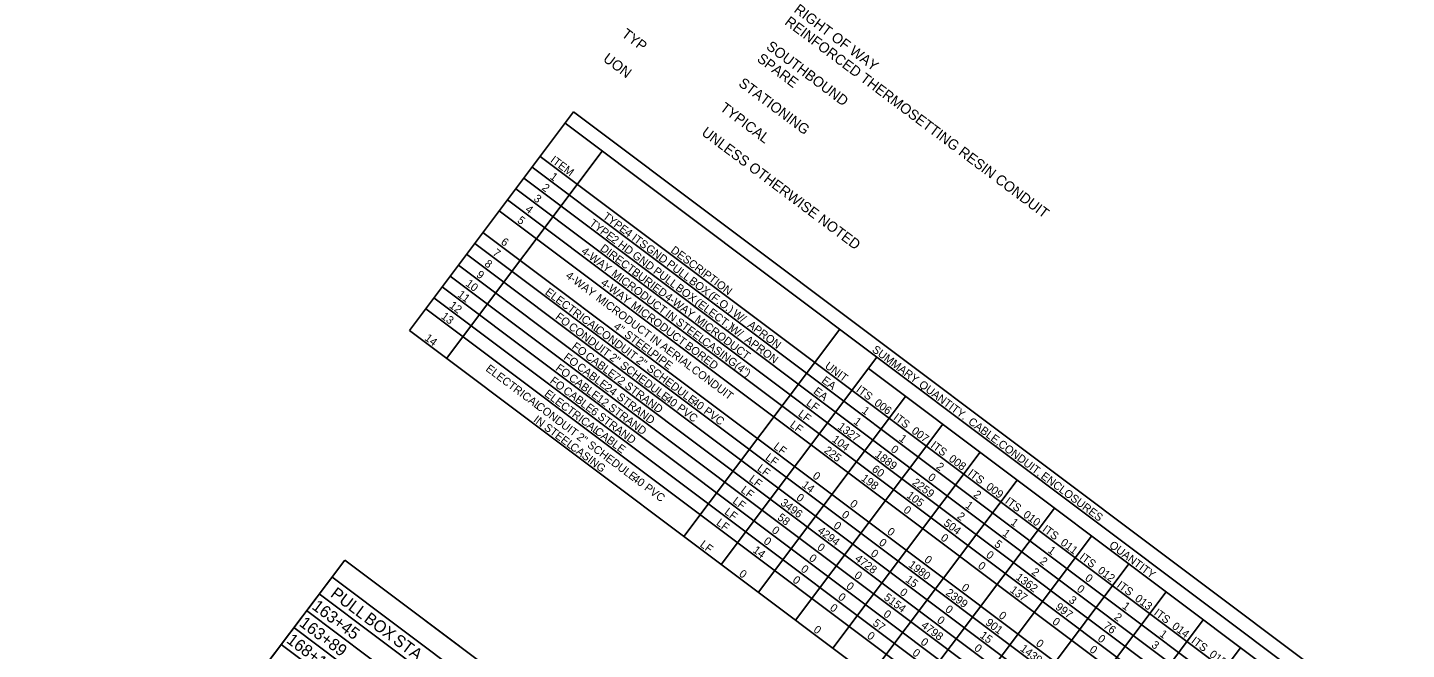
# Model space of a CAD drawing. Extents: x 626494 to 629419, y 365986 to 369334.
# Drawn here: x 627800.6 to 628284.5, y 368394.1 to 368612.5 of the extents above; entities that cross this region are included whole.
import ezdxf

# ---------------------------------------------------------------- set-up
doc = ezdxf.new("R2010")
doc.units = 0
for name, color, linetype in [('Default', 7, 'Continuous'), ('R_No Plot', 7, 'Continuous'), ('R_Shade Frontage Road', 7, 'Continuous')]:
    doc.layers.add(name, color=color, linetype=linetype)

msp = doc.modelspace()

# ---------------------------------------------------------------- linework, layer by layer
at = {"layer": 'Default'}
for p, q in [((627934.57, 368506.14), (627992.22, 368582.9)), ((627992.22, 368582.9), (627992.22, 368582.9)), ((627992.22, 368582.9), (628284.46, 368363.46)), ((627989.23, 368578.92), (628281.47, 368359.47)), ((627947.63, 368496.33), (628002.29, 368569.11)), ((627977.63, 368563.47), (628269.87, 368344.03)), ((627980.5, 368567.29), (628272.74, 368347.85)), ((627974.76, 368559.65), (628267, 368340.2)), ((627971.89, 368555.83), (628264.13, 368336.38)), ((627969.02, 368552.01), (628261.26, 368332.56)), ((627966.15, 368548.18), (628258.39, 368328.74)), ((627960.41, 368540.54), (628252.65, 368321.09)), ((627957.54, 368536.72), (628249.78, 368317.27)), ((627951.8, 368529.07), (628244.04, 368309.63)), ((627954.67, 368532.89), (628246.91, 368313.45)), ((627948.93, 368525.25), (628241.17, 368305.8)), ((627946.05, 368521.43), (628238.3, 368301.98)), ((627943.18, 368517.61), (628235.43, 368298.16)), ((627940.31, 368513.78), (628232.56, 368294.34)), ((627934.57, 368506.14), (628226.82, 368286.69)), ((628030.93, 368433.79), (628085.58, 368506.57)), ((628043.99, 368423.98), (628098.64, 368496.76)), ((628095.65, 368492.78), (628278.48, 368355.49)), ((628057.04, 368414.18), (628108.71, 368482.98)), ((628070.1, 368404.37), (628121.77, 368473.17)), ((628083.16, 368394.56), (628134.83, 368463.36)), ((628096.22, 368384.76), (628147.89, 368453.56)), ((628109.28, 368374.95), (628160.94, 368443.75)), ((628122.34, 368365.14), (628174, 368433.94)), ((627800.61, 368277.33), (627911.88, 368425.51)), ((627911.88, 368425.51), (628111.03, 368275.96)), ((628135.4, 368355.34), (628187.06, 368424.14)), ((627907.43, 368419.58), (628106.58, 368270.04)), ((627902.97, 368413.65), (628102.13, 368264.11)), ((628148.46, 368345.53), (628200.12, 368414.33)), ((627898.52, 368407.73), (628097.68, 368258.18)), ((628161.52, 368335.72), (628213.18, 368404.52)), ((627894.07, 368401.8), (628093.22, 368252.26)), ((627889.62, 368395.87), (628088.77, 368246.33)), ((628174.58, 368325.92), (628226.24, 368394.72))]:
    msp.add_line(p, q, dxfattribs=at)
at = {"layer": 'R_No Plot'}
msp.add_line((627911.88, 368425.51), (627911.88, 368425.51), dxfattribs=at)
msp.add_lwpolyline([(627911.88, 368425.51), (628234.33, 368183.37), (628185.91, 368118.88), (627863.45, 368361.02)], close=True, dxfattribs=at)

# ---------------------------------------------------------------- texts
at = {"layer": 'Default'}
for s, height, p in [('ITEM', 2.809, (627983.83, 368565.5)), ('1', 2.81, (627983.69, 368559.62)), ('3', 2.81, (627977.96, 368551.97)), ('2', 2.81, (627980.83, 368555.8)), ('4', 2.81, (627975.04, 368548.19)), ('5', 2.81, (627972.22, 368544.33)), ('TYPE', 2.809, (627997.49, 368543.28)), ('TYPE', 2.809, (628002.21, 368545.71)), (' 2', 2.809, (628004.31, 368538.16)), (' 4', 2.809, (628009.04, 368540.59)), (' ITS', 2.809, (628011.53, 368538.72)), ('7', 2.81, (627963.59, 368532.88)), ('6', 2.81, (627966.45, 368536.71)), ('4-WAY', 2.809, (627994.65, 368533.46)), ('DIRECT', 2.809, (628001.28, 368534.46)), (' HD', 2.809, (628006.71, 368536.36)), (' GND', 2.809, (628016.44, 368535.03)), ('DESCRIPTION', 2.8087, (628026.04, 368533.8)), ('8', 2.81, (627960.71, 368529.06)), (' GND', 2.809, (628011.73, 368532.59)), (' PULL', 2.809, (628023.77, 368529.52)), ('9', 2.81, (627957.86, 368525.22)), ('4-WAY', 2.809, (627989.2, 368524.89)), (' MICRODUCT', 2.809, (628004.39, 368526.15)), (' BURIED', 2.809, (628011.58, 368526.72)), (' PULL', 2.809, (628019.06, 368527.08)), (' BOX', 2.809, (628031.61, 368523.63)), ('11', 2.809, (627951.23, 368518.25)), ('10', 2.809, (627954.06, 368522.1)), ('ELECTRICAL', 2.809, (627981.95, 368519.09)), ('4-WAY', 2.809, (628001.5, 368522.34)), (' BOX', 2.809, (628026.9, 368521.19)), (' (F.O.)', 2.809, (628038.44, 368518.51)), ('12', 2.809, (627948.36, 368514.42)), (' MICRODUCT', 2.809, (627998.94, 368517.58)), (' MICRODUCT', 2.809, (628011.24, 368515.02)), (' 4-WAY', 2.809, (628023.13, 368518.05)), (' (ELECT.)', 2.809, (628033.72, 368516.07)), ('13', 2.809, (627945.5, 368510.6)), ('FO', 2.809, (627985.56, 368510.4)), (' IN', 2.809, (628023.29, 368511.95)), (' STEEL', 2.809, (628026.97, 368509.19)), (' MICRODUCT', 2.809, (628033.68, 368510.13)), (' W/', 2.809, (628046.91, 368512.15)), (' CONDUIT', 2.809, (627989.36, 368507.55)), (' CONDUIT', 2.809, (627998.71, 368506.5)), ('4"', 2.809, (628006, 368507)), (' STEEL', 2.809, (628008.94, 368504.79)), (' W/', 2.809, (628045.89, 368506.94)), (' APRON', 2.809, (628052.2, 368508.18)), ('14', 2.809, (627939.7, 368502.99)), ('FO', 2.809, (627991.39, 368500.04)), (' IN', 2.809, (628017.84, 368503.38)), (' AERIAL', 2.809, (628021.52, 368500.62)), (' BORED', 2.809, (628030.15, 368500.83)), (' CASING', 2.809, (628036.03, 368502.39)), (' APRON', 2.809, (628051.18, 368502.97)), ('SUMMARY', 2.809, (628096.7, 368498.92)), ('FO', 2.809, (627988.48, 368496.25)), (' CABLE', 2.809, (627995.19, 368497.19)), (' 2"', 2.809, (628003.71, 368496.77)), (' SCHEDULE', 2.809, (628007.45, 368493.96)), (' 2"', 2.809, (628013.06, 368495.73)), (' PIPE', 2.809, (628018.01, 368497.99)), ('UNIT', 2.809, (628080.14, 368493.17)), ('ELECTRICAL', 2.809, (627961.12, 368492.18)), ('FO', 2.809, (627985.65, 368492.4)), (' CABLE', 2.809, (627989.45, 368489.55)), (' CABLE', 2.809, (627992.27, 368493.4)), (' 72', 2.809, (628004.88, 368489.92)), (' SCHEDULE', 2.809, (628016.8, 368492.92)), (' CONDUIT', 2.809, (628032.41, 368492.44)), (' (4")', 2.809, (628047.54, 368493.74)), ('FO', 2.809, (627983.65, 368487.92)), (' CABLE', 2.809, (627987.45, 368485.07)), (' 24', 2.809, (628001.96, 368486.13)), (' STRAND', 2.809, (628009.07, 368486.77)), ('EA', 2.809, (628076.12, 368484.24)), ('EA', 2.809, (628078.99, 368488.06)), ('ITS_006', 2.809, (628091.15, 368484.9)), (' QUANTITY.', 2.809, (628112.29, 368487.22)), (' CONDUIT', 2.809, (627977.88, 368479.59)), ('ELECTRICAL', 2.809, (627981.73, 368483.38)), (' 12', 2.809, (627999.14, 368482.27)), (' STRAND', 2.809, (628006.24, 368482.91)), (' 40', 2.809, (628023.17, 368482.16)), (' 40', 2.809, (628032.52, 368481.11)), ('LF', 2.809, (628073.63, 368480.13)), ('IN', 2.809, (627977.89, 368474.32)), (' 6', 2.809, (627997.13, 368477.8)), (' STRAND', 2.809, (627999.59, 368475.96)), (' STRAND', 2.809, (628003.32, 368479.13)), (' PVC', 2.809, (628027.43, 368478.96)), (' PVC', 2.809, (628036.78, 368477.91)), ('LF', 2.809, (628070.76, 368476.31)), ('1', 2.81, (628093.1, 368477.46)), ('ITS_007', 2.809, (628104.22, 368475.09)), (' STEEL', 2.809, (627980.77, 368472.15)), (' CABLE', 2.809, (627998.49, 368470.8)), ('LF', 2.809, (628067.89, 368472.49)), ('1327', 2.809, (628084.66, 368471.85)), ('1', 2.81, (628090.23, 368473.64)), ('  CABLE,', 2.809, (628128.77, 368474.84)), (' CASING', 2.809, (627989.83, 368465.35)), (' 2"', 2.809, (627992.23, 368468.82)), (' SCHEDULE', 2.809, (627995.97, 368466.01)), ('LF', 2.809, (628062.15, 368464.84)), ('104', 2.809, (628082.66, 368467.38)), ('1', 2.81, (628106.16, 368467.66)), ('ITS_008', 2.809, (628117.27, 368465.29)), (' CONDUIT,', 2.809, (628140.08, 368466.34)), ('LF', 2.809, (628059.27, 368461.02)), ('225', 2.809, (628079.84, 368463.51)), ('1889', 2.809, (628097.73, 368462.03)), ('0', 2.81, (628103.26, 368463.86)), ('LF', 2.809, (628056.4, 368457.2)), ('0', 2.81, (628075.85, 368454.55)), ('60', 2.809, (628096.62, 368456.89)), ('2', 2.81, (628119.22, 368457.85)), ('ITS_009', 2.809, (628130.35, 368455.47)), (' ENCLOSURES', 2.8087, (628155.1, 368455.07)), (' 40', 2.809, (628011.69, 368454.2)), (' PVC', 2.809, (628015.95, 368451)), ('LF', 2.809, (628050.66, 368449.56)), ('LF', 2.809, (628053.53, 368453.38)), ('14', 2.809, (628072.07, 368451.41)), ('198', 2.809, (628092.87, 368453.73)), ('2259', 2.809, (628110.79, 368452.23)), ('0', 2.81, (628116.32, 368454.05)), ('LF', 2.809, (628047.79, 368445.73)), ('3496', 2.809, (628064.56, 368445.1)), ('0', 2.81, (628070.11, 368446.91)), ('105', 2.809, (628108.83, 368447.72)), ('2', 2.81, (628132.28, 368448.04)), ('ITS_010', 2.809, (628143.38, 368445.69)), ('LF', 2.809, (628044.92, 368441.91)), ('58', 2.809, (628063.48, 368439.93)), ('0', 2.81, (628086.04, 368440.93)), ('0', 2.81, (628088.91, 368444.75)), ('0', 2.81, (628107.71, 368442.59)), ('2', 2.81, (628126.54, 368440.4)), ('1', 2.81, (628129.41, 368444.22)), ('LF', 2.809, (628042.05, 368438.09)), ('0', 2.81, (628061.5, 368435.44)), ('0', 2.81, (628083.17, 368437.1)), ('504', 2.809, (628121.83, 368437.96)), ('1', 2.81, (628145.34, 368438.24)), ('ITS_011', 2.809, (628156.48, 368435.85)), ('LF', 2.809, (628036.31, 368430.44)), ('0', 2.81, (628058.63, 368431.62)), ('4294', 2.809, (628077.6, 368435.31)), ('0', 2.81, (628099.1, 368431.12)), ('0', 2.81, (628101.97, 368434.94)), ('0', 2.81, (628120.77, 368432.78)), ('5', 2.81, (628139.61, 368430.59)), ('1', 2.81, (628142.47, 368434.41)), ('14', 2.809, (628054.85, 368428.48)), ('0', 2.81, (628074.56, 368425.64)), ('0', 2.81, (628077.43, 368429.46)), ('0', 2.81, (628096.23, 368427.3)), ('0', 2.81, (628136.7, 368426.8)), ('1', 2.81, (628158.4, 368428.43)), ('ITS_012', 2.809, (628169.54, 368426.05)), ('QUANTITY', 2.809, (628179.9, 368430.22)), ('0', 2.81, (628071.69, 368421.82)), ('4728', 2.809, (628090.68, 368425.49)), ('1980', 2.809, (628109.47, 368423.33)), ('0', 2.81, (628115.03, 368425.14)), ('0', 2.81, (628133.83, 368422.97)), ('2', 2.81, (628152.66, 368420.78)), ('2', 2.81, (628155.53, 368424.61)), ('0', 2.81, (628050.02, 368420.15)), ('0', 2.81, (628068.82, 368417.99)), ('0', 2.81, (628087.62, 368415.83)), ('0', 2.81, (628090.49, 368419.65)), ('15', 2.809, (628108.43, 368418.13)), ('1362', 2.809, (628147.1, 368418.98)), ('0', 2.81, (628171.43, 368418.65)), ('ITS_013', 2.809, (628182.61, 368416.23)), ('PULL', 4.181, (627906.62, 368412.94)), ('0', 2.81, (628084.75, 368412.01)), ('5154', 2.809, (628100.85, 368411.87)), ('0', 2.81, (628106.42, 368413.67)), ('2399', 2.809, (628122.56, 368413.5)), ('0', 2.81, (628128.09, 368415.33)), ('137', 2.809, (628145.11, 368414.5)), ('0', 2.81, (628168.55, 368414.83)), ('163+45', 4.181, (627900.09, 368408.57)), ('0', 2.81, (628081.88, 368408.19)), ('0', 2.81, (628122.35, 368407.68)), ('997', 2.809, (628161.04, 368408.51)), ('3', 2.81, (628165.73, 368410.97)), ('1', 2.81, (628184.52, 368408.82)), ('ITS_014', 2.809, (628195.61, 368406.47)), ('163+89', 4.181, (627895.64, 368402.65)), (' BOX', 4.181, (627917.1, 368405.06)), ('57', 2.809, (628096.93, 368402.86)), ('0', 2.81, (628100.68, 368406.02)), ('4798', 2.809, (628113.93, 368402.05)), ('0', 2.81, (628119.48, 368403.86)), ('901', 2.809, (628136.52, 368403.02)), ('0', 2.81, (628141.14, 368405.52)), ('0', 2.81, (628159.94, 368403.36)), ('76', 2.809, (628177.86, 368401.87)), ('2', 2.81, (628181.65, 368404.99)), ('168+14', 4.181, (627891.18, 368396.72)), (' STA.', 4.181, (627927.26, 368397.44)), ('0', 2.81, (628076.14, 368400.54)), ('0', 2.81, (628094.94, 368398.38)), ('15', 2.809, (628134.55, 368398.52)), ('0', 2.81, (628175.87, 368397.38)), ('1', 2.81, (628197.58, 368399.01)), ('ITS_015', 2.809, (628208.72, 368396.62)), ('0', 2.81, (628110.86, 368392.4)), ('0', 2.81, (628113.73, 368396.22)), ('0', 2.81, (628132.53, 368394.06)), ('1439', 2.809, (628148.67, 368393.89)), ('0', 2.81, (628154.2, 368395.72)), ('0', 2.81, (628173, 368393.55)), ('3', 2.81, (628194.72, 368395.18))]:
    msp.add_text(s, height=height, rotation=323.0968, dxfattribs=at).set_placement(p)
at = {"layer": 'R_Shade Frontage Road'}
for s, p in [('REINFORCED THERMOSETTING RESIN CONDUIT', (628066.01, 368613.9)), ('RIGHT OF WAY', (628069.25, 368618.22)), ('TYP', (628008.77, 368609.61)), ('SOUTHBOUND', (628059.53, 368605.26)), ('UON', (628002.28, 368600.98)), ('SPARE', (628056.28, 368600.94)), ('STATIONING', (628049.8, 368592.31)), ('TYPICAL', (628043.31, 368583.67)), ('UNLESS OTHERWISE NOTED', (628036.83, 368575.04))]:
    msp.add_text(s, height=3.6, rotation=323.0968, dxfattribs=at).set_placement(p)

doc.saveas('drawing.dxf')
